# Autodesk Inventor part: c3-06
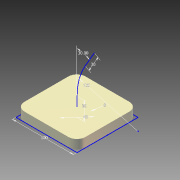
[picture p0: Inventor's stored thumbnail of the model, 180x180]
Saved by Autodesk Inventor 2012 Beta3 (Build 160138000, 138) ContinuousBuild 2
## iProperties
Created: 2010-11
Part Number: c3-06
Material: Cast Iron
Document SubType Name: Modeling
Designer: Beta-8540w
Density: 7.25 g/cm^3
Mass: 1087.5 g
Surface Area: 260 cm^2
Volume: 150 cm^3
Author: Beta-8540w
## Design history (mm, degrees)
sketch "Sketch1"
  geometry: L1 (-50, -50)-(50, -50); L2 (50, -50)-(50, 50); L3 (50, 50)-(-50, 50); L4 (-50, 50)-(-50, -50); C1 r 20 at (0, 0); C2 r 28 at (0, 0); 3 further points
  constraints: 8 end point, 3 perpendicular, 2 centre point, 2 coincident, 2 midpoint, 1 horizontal, 1 horizontal alignment, 1 parallel, 1 vertical alignment
  dimensions: "Width" = 100 distance of L1.start L1.end; "d6" = 40 diameter of C1; "d7" = 8 radial gap between concentric circles of C2 C1
extrude "Extrusion1" new body sketch "Sketch1" distance "d3" = 15; taper "d4" = 0 deg
fillet "Fillet1" dims "d5" = 14
sketch "Sketch2"
  geometry: L1 (0, 0)-(0, 30); L2 (-13.397, 80)-(-28.397, 105.981); A1 r 100 centre (-100, 30) between (0, 30) and (-13.397, 80)
  constraints: 4 end point, 2 point on circle, 2 tangent, 1 centre point, 1 vertical
  dimensions: "d8" = 30 distance of L1.start L1.end; "d9" = 100 radius of A1; "d10" = 30 distance of L2.start L2.end; "d11" = 30 deg angle of L2 L1
body "Solid1"
